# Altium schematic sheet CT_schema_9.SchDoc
size 278 x 170 mm
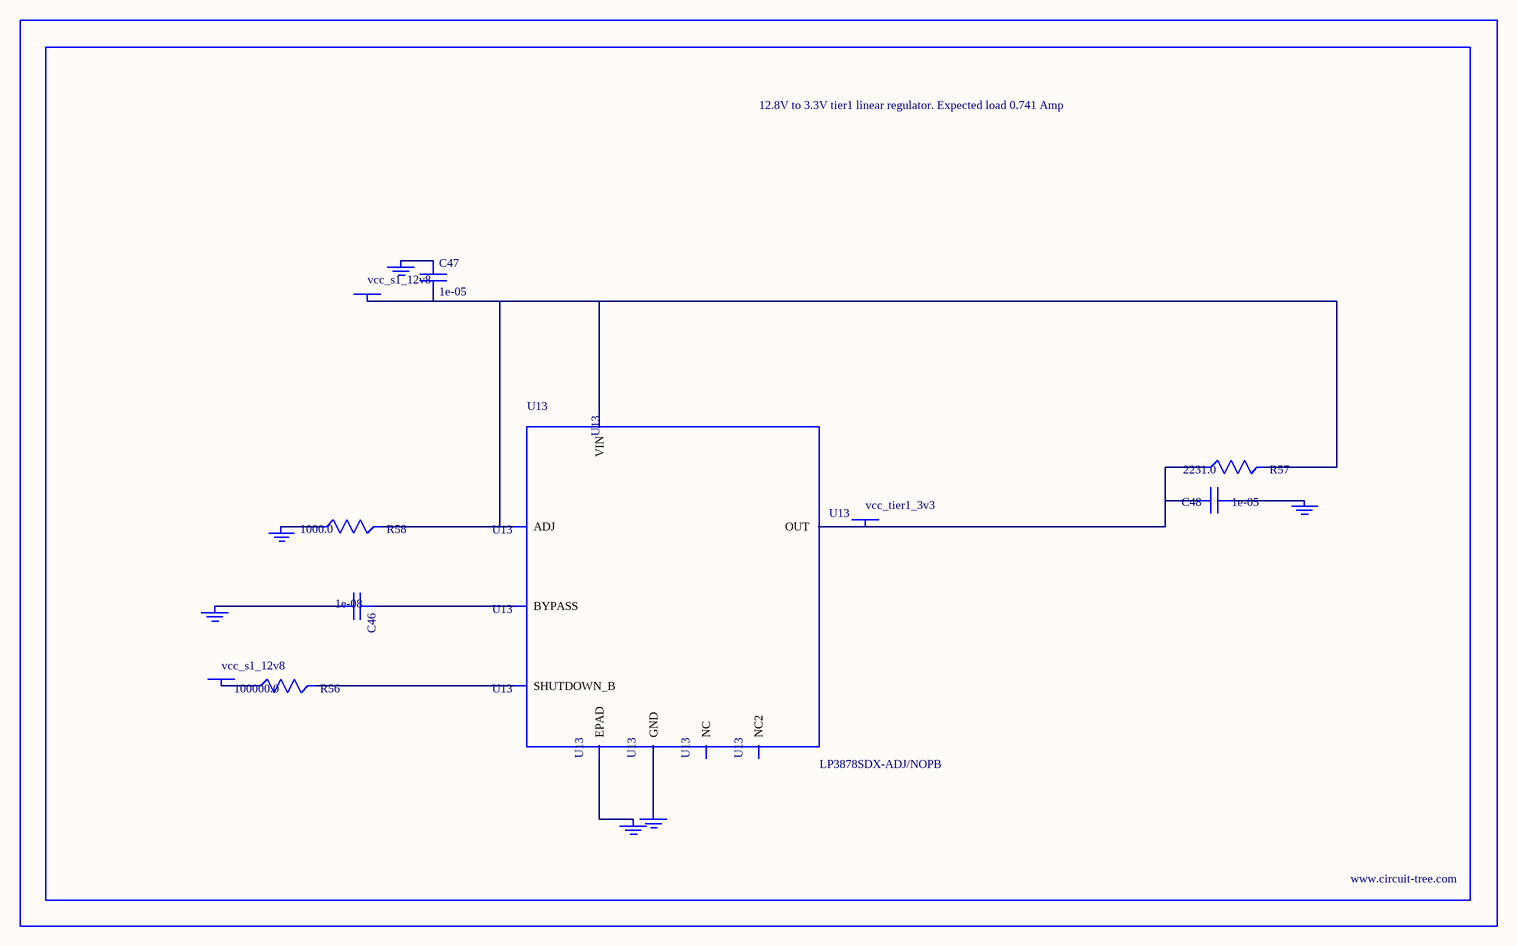
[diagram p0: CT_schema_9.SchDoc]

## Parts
BORDER8  (no value)
C46  1e-08  [C0402]
C47  1e-05  [C1210]
C48  1e-05  [C1210]
GND_INSTANCE_8_0  (no value)
GND_INSTANCE_8_1  (no value)
GND_INSTANCE_8_2  (no value)
GND_INSTANCE_8_3  (no value)
GND_INSTANCE_8_4  (no value)
GND_INSTANCE_8_5  (no value)
POWER_INSTANCE_8_0  vcc_s1_12v8
POWER_INSTANCE_8_1  vcc_s1_12v8
POWER_INSTANCE_8_2  vcc_tier1_3v3
R56  100000.0  [R0603]
R57  2231.0  [R0603]
R58  1000.0  [R0603]
U13  LP3878SDX-ADJ/NOPB  [WSON-8]

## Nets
NetC46_1: C46.1 U13.1(BYPASS)
NetC46_2: C46.2 GND_INSTANCE_8_0.0(GND)
NetC47_1: C47.1 GND_INSTANCE_8_1.0(GND)
NetC47_2: C47.2 POWER_INSTANCE_8_0.0(PWR) R57.2 R58.2 U13.4(VIN) U13.6(ADJ)
NetC48_1: C48.1 GND_INSTANCE_8_2.0(GND)
NetC48_2: C48.2 POWER_INSTANCE_8_2.0(PWR) R57.1 U13.5(OUT)
NetGND_INSTANCE_8_3_0: GND_INSTANCE_8_3.0(GND) R58.1
NetGND_INSTANCE_8_4_0: GND_INSTANCE_8_4.0(GND) U13.PAD(EPAD)
NetGND_INSTANCE_8_5_0: GND_INSTANCE_8_5.0(GND) U13.3(GND)
NetPOWER_INSTANCE_8_1_0: POWER_INSTANCE_8_1.0(PWR) R56.1
NetR56_2: R56.2 U13.8(SHUTDOWN_B)

Not connected (* = marked no-connect by the designer): U13 2(NC) 7(NC2)

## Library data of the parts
BORDER8 = BORDER_PAGE8
C46 = C0402C103K3RAC
C47 = C1210C106K5PACTU
C48 = GRM32DR61E106MA12L
GND_INSTANCE_8_0-GND_INSTANCE_8_5 = GND
POWER_INSTANCE_8_0-POWER_INSTANCE_8_2 = PWR
R56 = RC0603JR-07100KL
R57 = R57
R58 = RC0603JR-071KL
